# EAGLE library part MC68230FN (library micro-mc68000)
68xxx PROCESSOR
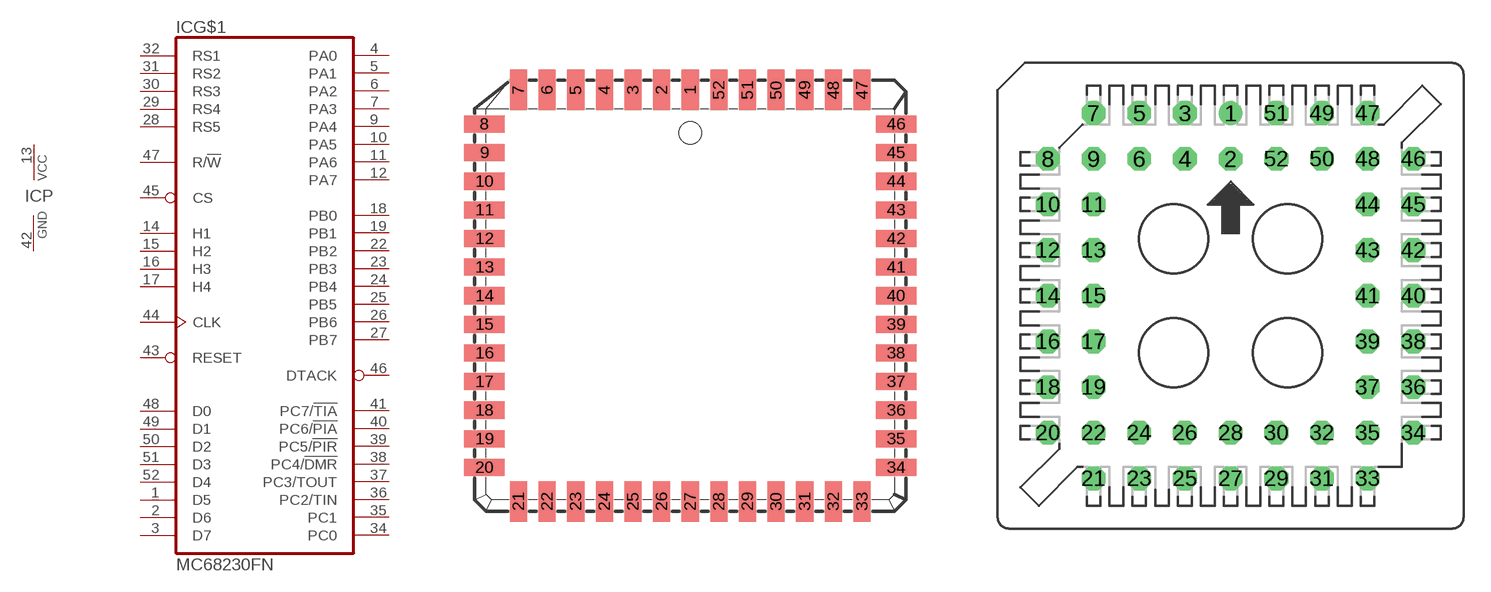
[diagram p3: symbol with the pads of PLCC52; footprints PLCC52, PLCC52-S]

Designator prefix IC; gates G$1=68230 P=PWRN

## MC68230FN (OC_FARNELL: unknown; OC_NEWARK: unknown)  [PLCC52]
1  G$1:D5
2  G$1:D6
3  G$1:D7
4  G$1:PA0
5  G$1:PA1
6  G$1:PA2
7  G$1:PA3
9  G$1:PA4
10  G$1:PA5
11  G$1:PA6
12  G$1:PA7
13  P:VCC  pwr
14  G$1:H1  in
15  G$1:H2
16  G$1:H3  in
17  G$1:H4
18  G$1:PB0
19  G$1:PB1
22  G$1:PB2
23  G$1:PB3
24  G$1:PB4
25  G$1:PB5
26  G$1:PB6
27  G$1:PB7
28  G$1:RS5  in
29  G$1:RS4  in
30  G$1:RS3  in
31  G$1:RS2  in
32  G$1:RS1  in
34  G$1:PC0
35  G$1:PC1
36  G$1:PC2/TIN
37  G$1:PC3/TOUT
38  G$1:PC4/!DMR
39  G$1:PC5/!PIR
40  G$1:PC6/!PIA
41  G$1:PC7/!TIA
42  P:GND  pwr
43  G$1:RESET  in
44  G$1:CLK  in
45  G$1:CS  in
46  G$1:DTACK  out
47  G$1:R/!W  in
48  G$1:D0
49  G$1:D1
50  G$1:D2
51  G$1:D3
52  G$1:D4

## MC68230FN-SOC (OC_FARNELL: unknown; OC_NEWARK: unknown)  [PLCC52-S]
Pads as for PLCC52

## Footprint PLCC52 (pad centres in mm)
PLASTIC LEADED CHIP CARRIER square
smd 0.76 x 1.8: 1 0,9.13; 2 -1.27,9.13; 3 -2.54,9.13; 4 -3.81,9.13; 5 -5.08,9.13; 6 -6.35,9.13; 7 -7.62,9.13; 21 -7.62,-9.13; 22 -6.35,-9.13; 23 -5.08,-9.13; 24 -3.81,-9.13; 25 -2.54,-9.13; 26 -1.27,-9.13; 27 0,-9.13; 28 1.27,-9.13; 29 2.54,-9.13; 30 3.81,-9.13; 31 5.08,-9.13; 32 6.35,-9.13; 33 7.62,-9.13; 47 7.62,9.13; 48 6.35,9.13; 49 5.08,9.13; 50 3.81,9.13; 51 2.54,9.13; 52 1.27,9.13
smd 1.8 x 0.76: 8 -9.13,7.62; 9 -9.13,6.35; 10 -9.13,5.08; 11 -9.13,3.81; 12 -9.13,2.54; 13 -9.13,1.27; 14 -9.13,0; 15 -9.13,-1.27; 16 -9.13,-2.54; 17 -9.13,-3.81; 18 -9.13,-5.08; 19 -9.13,-6.35; 20 -9.13,-7.62; 34 9.13,-7.62; 35 9.13,-6.35; 36 9.13,-5.08; 37 9.13,-3.81; 38 9.13,-2.54; 39 9.13,-1.27; 40 9.13,0; 41 9.13,1.27; 42 9.13,2.54; 43 9.13,3.81; 44 9.13,5.08; 45 9.13,6.35; 46 9.13,7.62

## Footprint PLCC52-S (pad centres in mm)
PLCC Socked
drill 0.813 round: 1 0,10.16
drill 0.813 octagon: 2 0,7.62; 3 -2.54,10.16; 4 -2.54,7.62; 5 -5.08,10.16; 6 -5.08,7.62; 7 -7.62,10.16; 8 -10.16,7.62; 9 -7.62,7.62; 10 -10.16,5.08; 11 -7.62,5.08; 12 -10.16,2.54; 13 -7.62,2.54; 14 -10.16,0; 15 -7.62,0; 16 -10.16,-2.54; 17 -7.62,-2.54; 18 -10.16,-5.08; 19 -7.62,-5.08; 20 -10.16,-7.62; 21 -7.62,-10.16; 22 -7.62,-7.62; 23 -5.08,-10.16; 24 -5.08,-7.62; 25 -2.54,-10.16; 26 -2.54,-7.62; 27 0,-10.16; 28 0,-7.62; 29 2.54,-10.16; 30 2.54,-7.62; 31 5.08,-10.16; 32 5.08,-7.62; 33 7.62,-10.16; 34 10.16,-7.62; 35 7.62,-7.62; 36 10.16,-5.08; 37 7.62,-5.08; 38 10.16,-2.54; 39 7.62,-2.54; 40 10.16,0; 41 7.62,0; 42 10.16,2.54; 43 7.62,2.54; 44 7.62,5.08; 45 10.16,5.08; 46 10.16,7.62; 47 7.62,10.16; 48 7.62,7.62; 49 5.08,10.16; 50 5.08,7.62; 51 2.54,10.16; 52 2.54,7.62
